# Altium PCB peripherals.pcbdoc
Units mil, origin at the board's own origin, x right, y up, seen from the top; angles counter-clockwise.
Board outline 1893.7 x 3125 mil, 2 copper layers (Top Layer, Bottom Layer); 4 components, 12 nets, 35 pads, 112 vias.
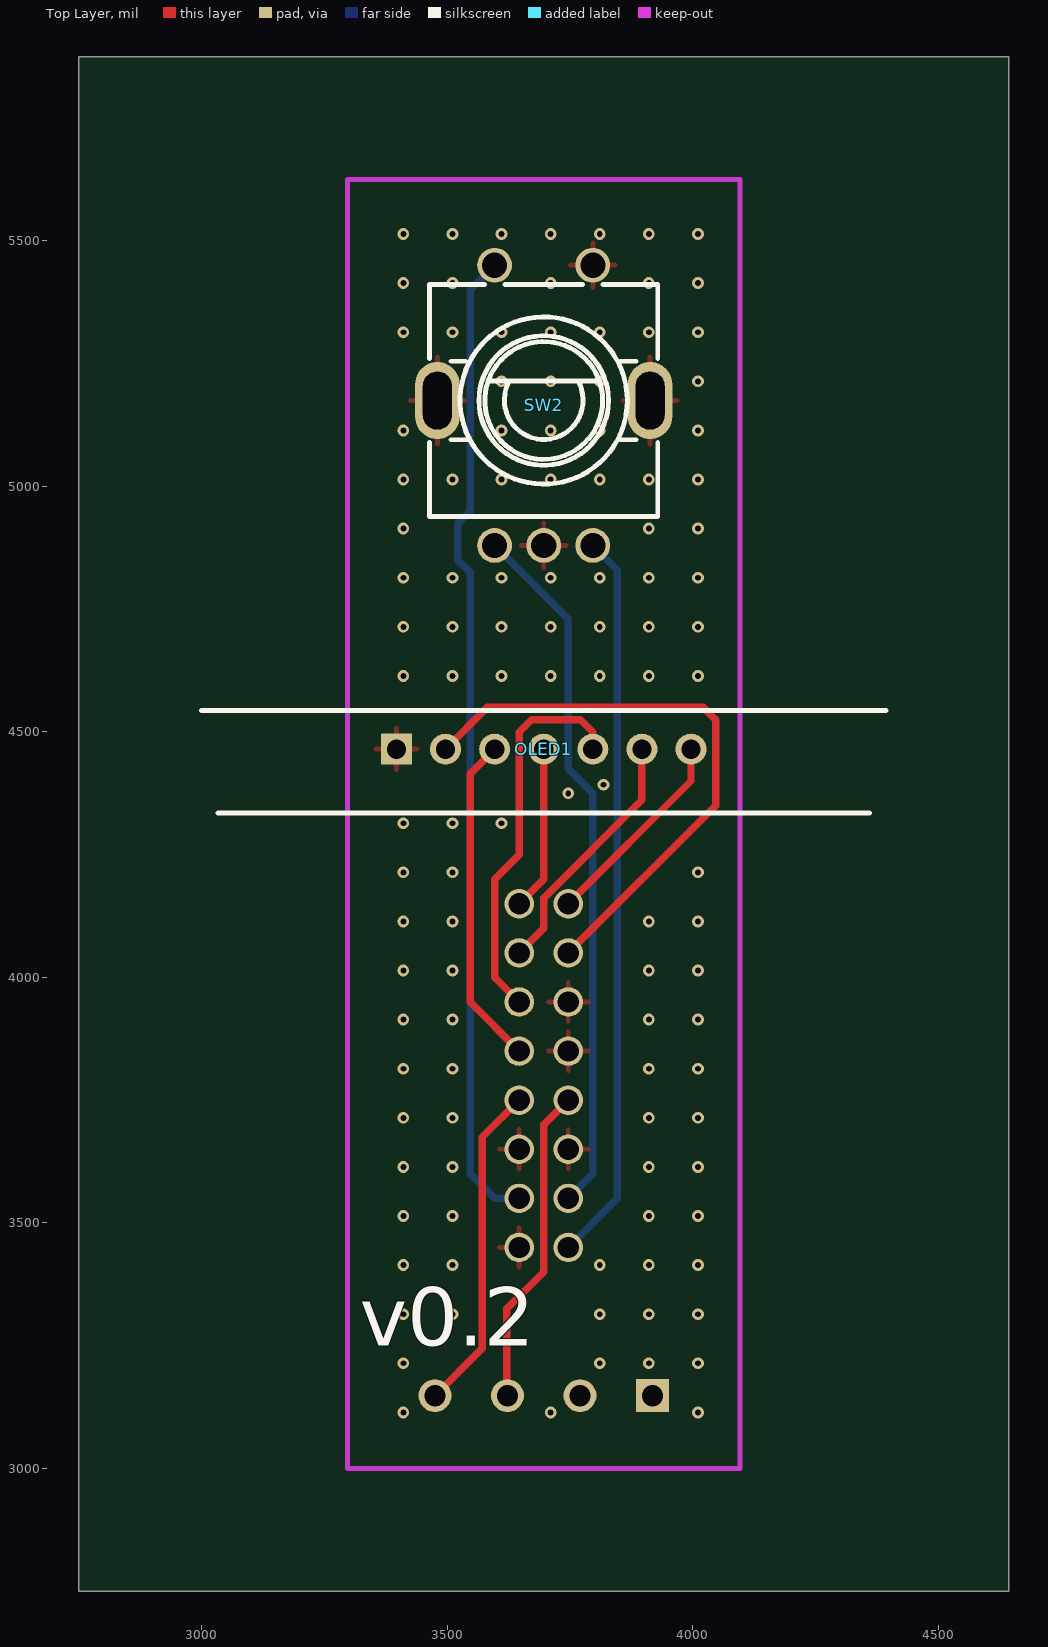
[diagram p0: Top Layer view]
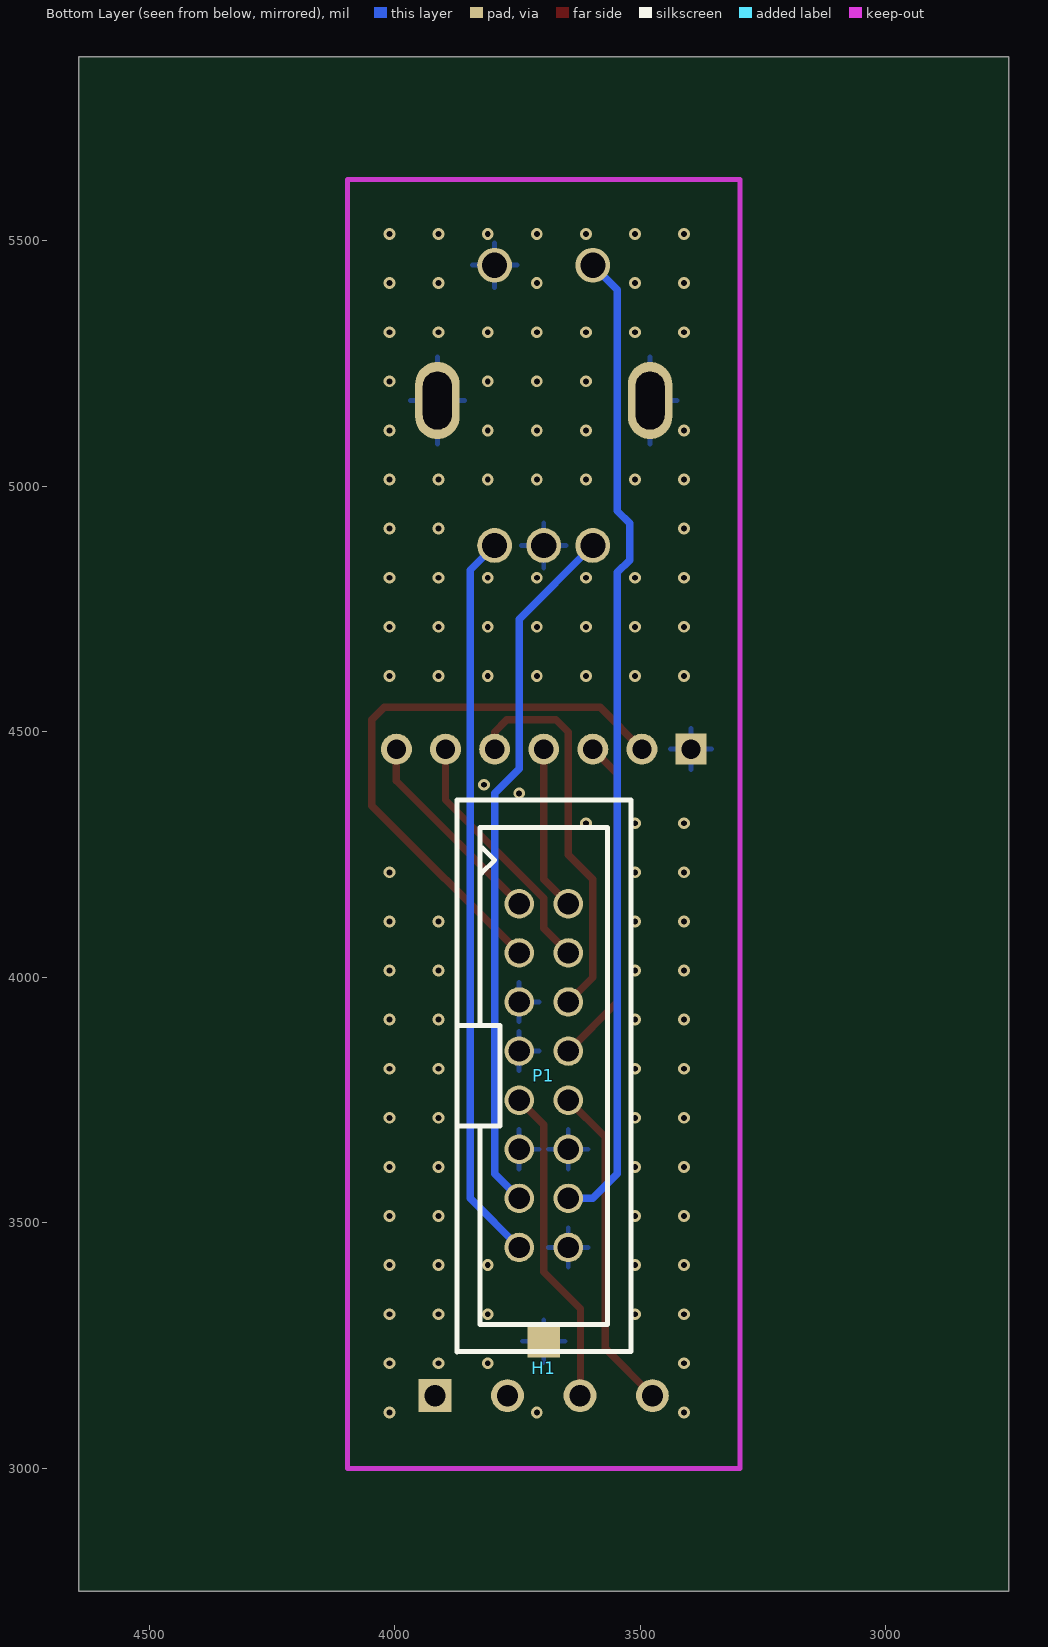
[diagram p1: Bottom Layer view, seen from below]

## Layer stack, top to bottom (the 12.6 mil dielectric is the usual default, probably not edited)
Top Layer: signal copper (thickness not stored)
Dielectric: dielectric 12.6, FR-4, Dk 4.8
Bottom Layer: signal copper (thickness not stored)

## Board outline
4643.7,2750 2750,2750 2750,5875 4643.7,5875

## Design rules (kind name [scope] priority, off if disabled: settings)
BoardOutlineClearance copperThickness1oz [All] p0: genericclearance=10 ignorepadtopadclearanceinfootprint=FALSE except(0: Arc-SplitContinuation Track-SplitContinuation SMDPad-SplitContinuation THPad-SplitContinuation Via-SplitContinuation Fill-SplitContinuation Poly-SplitContinuation Region-SplitContinuation Text-SplitContinuation; 6: Track-CutoutEdge SMDPad-CutoutEdge THPad-CutoutEdge Via-CutoutEdge Region-CutoutEdge; 11.8: Track-OutlineEdge SMDPad-OutlineEdge THPad-OutlineEdge Via-OutlineEdge Fill-OutlineEdge Region-OutlineEdge Poly-OutlineEdge Text-OutlineEdge Fill-CutoutEdge)
BoardOutlineClearance copperThickness2oz [All] p0: genericclearance=10 ignorepadtopadclearanceinfootprint=FALSE except(0: Arc-SplitContinuation Track-SplitContinuation SMDPad-SplitContinuation THPad-SplitContinuation Via-SplitContinuation Fill-SplitContinuation Poly-SplitContinuation Region-SplitContinuation Text-SplitContinuation; 6: Track-CutoutEdge SMDPad-CutoutEdge THPad-CutoutEdge Via-CutoutEdge Region-CutoutEdge; 11.8: Track-OutlineEdge SMDPad-OutlineEdge THPad-OutlineEdge Via-OutlineEdge Fill-OutlineEdge Region-OutlineEdge Poly-OutlineEdge Text-OutlineEdge Fill-CutoutEdge)
Clearance copperThickness1oz [(InNet('GND') OR InNet('VCC') OR InNet('$1N2949') OR InNet('$1N2960') OR InNet('$1N2859') OR InNet('$1N1183') OR InNet('$1N2908') OR InNet('$1N2911') OR InNet('$1N2932') OR InNet('$1N3145') OR InNet('$1N3527') OR InNet('$1N3518'))] p1: gap=7 ignorepadtopadclearanceinfootprint=FALSE except(4: Track-Track; 6: Track-SMDPad SMDPad-SMDPad Track-THPad SMDPad-THPad THPad-THPad Track-Via SMDPad-Via THPad-Via Via-Via SMDPad-Fill THPad-Fill Via-Fill Fill-Fill Track-Region SMDPad-Region THPad-Region Via-Region Region-Region Track-Poly SMDPad-Poly THPad-Poly Via-Poly Fill-Poly Region-Poly Poly-Poly Track-Text SMDPad-Text THPad-Text Via-Text Fill-Text Region-Text Poly-Text Text-Text; 6.9: Track-Hole SMDPad-Hole THPad-Hole Via-Hole Fill-Hole Region-Hole Poly-Hole Text-Hole Sheet-Hole; 11.8: Track-Fill Fill-Region Track-Sheet SMDPad-Sheet THPad-Sheet Via-Sheet Fill-Sheet Region-Sheet Poly-Sheet Text-Sheet)
Clearance copperThickness2oz [All] p1: gap=7 ignorepadtopadclearanceinfootprint=FALSE except(6: Track-SMDPad SMDPad-SMDPad Track-THPad SMDPad-THPad THPad-THPad Track-Via SMDPad-Via THPad-Via Via-Via SMDPad-Fill THPad-Fill Via-Fill Fill-Fill Track-Region SMDPad-Region THPad-Region Via-Region Region-Region Track-Poly SMDPad-Poly THPad-Poly Via-Poly Fill-Poly Region-Poly Poly-Poly Track-Text SMDPad-Text THPad-Text Via-Text Fill-Text Region-Text Poly-Text Text-Text; 6.9: Track-Hole SMDPad-Hole THPad-Hole Via-Hole Fill-Hole Region-Hole Poly-Hole Text-Hole Sheet-Hole; 8: Track-Track; 11.8: Track-Fill Fill-Region Track-Sheet SMDPad-Sheet THPad-Sheet Via-Sheet Fill-Sheet Region-Sheet Poly-Sheet Text-Sheet)
DiffPairsRouting differentialPair [All] p1: maxuncoupledlength=10 minlimit=6 maxlimit=6 mostfreqgap=6 toplayer_minwidth=5 toplayer_prefwidth=10 toplayer_maxwidth=100 bottomlayer_minwidth=5 bottomlayer_prefwidth=10 bottomlayer_maxwidth=100
PasteMaskExpansion pasteMaskExpansion [All] p1: expansion=0
PlaneConnect innerPlane [All] p1: planeconnectstyle=Relief reliefexpansion=20 reliefentries=4 reliefconductorwidth=10 reliefairgap=10
PolygonConnect copperRegion [All] p1: connectstyle=Relief reliefentries=4 reliefconductorwidth=10 polygonreliefangle="90 Angle" airgapwidth=10
RoutingVias viaSize [All] p1: viastyle="Through Hole" holewidth=12.0078 minholewidth=11.811 maxholewidth=248.0314 width=24.0158 minwidth=19.685 maxwidth=393.7008
SolderMaskExpansion solderMaskExpansion [All] p1: useseparateexpansions=TRUE expansion=2 expansionbottom=2
Width copperThickness1oz [All] p1: maxlimit=100 minlimit=5 preferedwidth=10
Width copperThickness2oz [All] p1: maxlimit=100 minlimit=8 preferedwidth=10

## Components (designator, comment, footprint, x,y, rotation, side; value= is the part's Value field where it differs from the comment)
H1 "HDR-M_2.54_1x5P" HDR-TH_5P-P2.54-V-M 3696.85,3148.23 r180 bottom
OLED1 "HS13L02W4S01" OLED-TH_HS13L02W4S01 3696.85,4465 r0 top
P1 "2.54-2*8P简牛" IDC-TH_16P-P2.54_C3406 3696.85,3800 r270 bottom
SW2 "EC11E15244B2" SW-TH_EC11XXXXXXXX 3696.85,5165.2 r0 top

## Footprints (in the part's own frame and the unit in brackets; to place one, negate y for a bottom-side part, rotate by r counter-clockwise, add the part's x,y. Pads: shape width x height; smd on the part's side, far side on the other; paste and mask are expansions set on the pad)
HDR-TH_5P-P2.54-V-M [mm]
  rect 1.7x1.7 hole 1.1: 1(-5.625,0)
  round 1.7 hole 1.1: 2(-1.875,0) 3(1.875,0) 4(5.625,0)
  rect 1.7x1.7 smd: 5(0,2.813)
IDC-TH_16P-P2.54_C3406 [mil]
  round 60 hole 43.3: 1(-350,-50) 2(-350,50) 3(-250,-50) 4(-250,50) 5(-150,-50) 6(-150,50) 7(-50,-50) 8(-50,50) 9(50,-50) 10(50,50) 11(150,-50) 12(150,50) 13(250,-50) 14(250,50) 15(350,-50) 16(350,50)
  silkscreen extent -561,-177 563,178
OLED-TH_HS13L02W4S01 [mm]
  rect 1.6x1.6 hole 1: 1(-7.62,0)
  round 1.6 hole 1: 2(-5.08,0) 3(-2.54,0) 4(0,0) 5(2.54,0) 6(5.08,0) 7(7.62,0)
  silkscreen extent -17.7,-3.3 17.7,2
SW-TH_EC11XXXXXXXX [mm]
  oval 2.3x4 hole 1.5 slot 3 at 90 deg: 6(5.5,0.25) 7(-5.5,0.25)
  round 1.8 hole 1.3: A(-2.54,-7.25) B(2.54,-7.25) C(0,-7.25) D(-2.54,7.25) E(2.54,7.25)
  silkscreen extent -5.9,-5.75 5.9,6.25

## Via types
v1: diameter 24.02, hole 12.01, Top Layer to Bottom Layer, 112 vias

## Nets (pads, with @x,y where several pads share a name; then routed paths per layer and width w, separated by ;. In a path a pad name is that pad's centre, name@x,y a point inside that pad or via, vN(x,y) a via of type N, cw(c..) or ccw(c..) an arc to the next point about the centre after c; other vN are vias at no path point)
$1N1183: OLED1.4 P1.2 | length 335.7
  Top Layer w15: P1.2 3696.85,4200 OLED1.4
$1N2859: OLED1.3 P1.8 | length 677.1
  Top Layer w15: OLED1.3 3546.85,4415 3546.85,3950 P1.8
$1N2908: OLED1.5 P1.6 | length 797.1
  Top Layer w15: P1.6 3596.85,4000 3596.85,4200 3646.85,4250 3646.85,4500 3671.85,4525 3771.85,4525 3796.85,4500 OLED1.5
$1N2911: OLED1.6 P1.4 | length 518.6
  Top Layer w15: P1.4 3696.85,4100 3696.85,4161.5 3896.85,4361.5 OLED1.6
$1N2932: OLED1.7 P1.1 | length 418.6
  Top Layer w15: P1.1 3996.85,4400 OLED1.7
$1N2949: H1.4 P1.10 | length 672.8
  Top Layer w15: H1.4 3571.85,3244.68 3571.85,3675 P1.10
$1N2960: H1.3 P1.9 | length 654
  Top Layer w15: H1.3 3621.85,3149.41 3621.85,3325 3696.85,3400 3696.85,3700 P1.9
$1N3145: P1.14 SW2.D | length 2012.8
  Bottom Layer w15: SW2.D 3546.85,5400.64 3546.85,4950 3521.85,4925 3521.85,4850 3546.85,4825 3546.85,3600 3596.85,3550 P1.14
$1N3518: P1.15 SW2.B | length 1491.9
  Bottom Layer w15: P1.15 3846.85,3550 3846.85,4829.76 SW2.B
$1N3527: P1.13 SW2.A | length 1433.3
  Bottom Layer w15: SW2.A 3746.85,4729.76 3746.85,4425 3796.85,4375 3796.85,3600 P1.13
GND: H1.5 OLED1.1 P1.5 P1.7 P1.11 P1.12 P1.16 SW2.6 SW2.7 SW2.C SW2.E
  other v1: 3410.95,3114.1 3710.95,3114.1 4010.95,3114.1 3410.95,3214.1 3810.95,3214.1 3910.95,3214.1 4010.95,3214.1 3410.95,3314.1 3510.95,3314.1 3810.95,3314.1 3910.95,3314.1 4010.95,3314.1 3410.95,3414.1 3510.95,3414.1 3810.95,3414.1 3910.95,3414.1 4010.95,3414.1 3410.95,3514.1 3510.95,3514.1 3910.95,3514.1 4010.95,3514.1 3410.95,3614.1 3510.95,3614.1 3910.95,3614.1 4010.95,3614.1 3410.95,3714.1 3510.95,3714.1 3910.95,3714.1 4010.95,3714.1 3410.95,3814.1 3510.95,3814.1 3910.95,3814.1 4010.95,3814.1 3410.95,3914.1 3510.95,3914.1 3910.95,3914.1 4010.95,3914.1 3410.95,4014.1 3510.95,4014.1 3910.95,4014.1 4010.95,4014.1 3410.95,4114.1 3510.95,4114.1 3910.95,4114.1 4010.95,4114.1 3410.95,4214.1 3510.95,4214.1 4010.95,4214.1 3410.95,4314.1 3510.95,4314.1 3610.95,4314.1 3746.85,4375 3818.45,4392.46 3410.95,4614.1 3510.95,4614.1 3610.95,4614.1 3710.95,4614.1 3810.95,4614.1 3910.95,4614.1 4010.95,4614.1 3410.95,4714.1 3510.95,4714.1 3610.95,4714.1 3710.95,4714.1 3810.95,4714.1 3910.95,4714.1 4010.95,4714.1 3410.95,4814.1 3510.95,4814.1 3610.95,4814.1 3710.95,4814.1 3810.95,4814.1 3910.95,4814.1 4010.95,4814.1 3410.95,4914.1 3910.95,4914.1 4010.95,4914.1 3410.95,5014.1 3510.95,5014.1 3610.95,5014.1 3710.95,5014.1 3810.95,5014.1 3910.95,5014.1 4010.95,5014.1 3410.95,5114.1 3610.95,5114.1 3710.95,5114.1 3810.95,5114.1 4010.95,5114.1 3610.95,5214.1 3710.95,5214.1 3810.95,5214.1 4010.95,5214.1 3410.95,5314.1 3510.95,5314.1 3610.95,5314.1 3710.95,5314.1 3810.95,5314.1 3910.95,5314.1 4010.95,5314.1 3410.95,5414.1 3510.95,5414.1 3710.95,5414.1 3910.95,5414.1 4010.95,5414.1 3410.95,5514.1 3510.95,5514.1 3610.95,5514.1 3710.95,5514.1 3810.95,5514.1 3910.95,5514.1 4010.95,5514.1
VCC: OLED1.2 P1.3 | length 1194.8
  Top Layer w15: OLED1.2 3581.85,4550 4021.85,4550 4046.85,4525 4046.85,4350 P1.3
pads on no net: H1.1 H1.2

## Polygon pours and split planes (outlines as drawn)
GND on Bottom Layer (solid, remove dead copper, pour order 2): 3296.85,5625 4096.85,5625 4096.85,3000 3296.85,3000
GND on Top Layer (solid, remove dead copper, pour order 0): 3296.85,5625 4096.85,5625 4096.85,3000 3296.85,3000

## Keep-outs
Board Outline Layer:
  lines w10: 3296.85,3000 4096.85,3000 4096.85,5625 3296.85,5625 3296.85,3000

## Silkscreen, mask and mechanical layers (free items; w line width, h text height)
Top Silkscreen Layer:
  text "v0.2" at 3321.85,3250 h120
